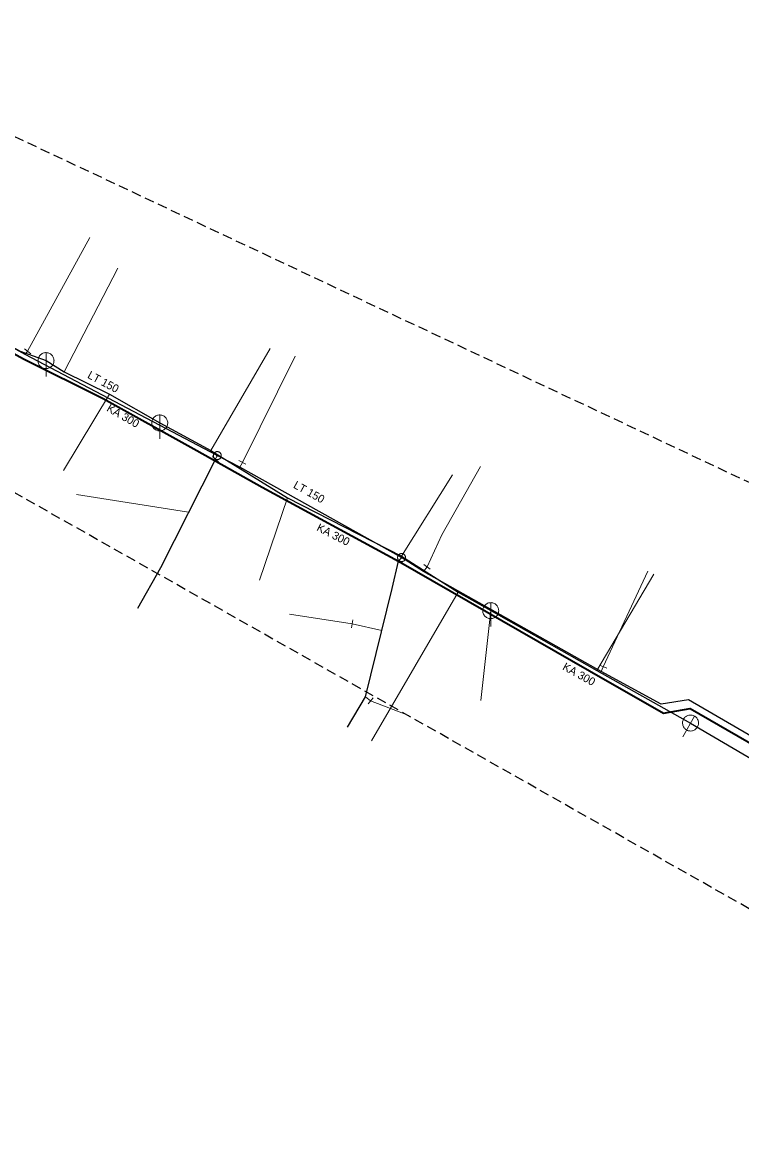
# Model space of a CAD drawing. Extents: x -749365 to -748625, y -965388 to -964881.
# Drawn here: x -749302.4 to -749212.4, y -965022.6 to -964883.5 of the extents above; entities that cross this region are included whole.
import ezdxf

# ---------------------------------------------------------------- set-up
doc = ezdxf.new("R2010")
doc.units = 0
doc.header["$LTSCALE"] = 0.4
doc.linetypes.add('MEDIUM_DASHED', pattern=[4.5, 3, -1.5])
for name, color, linetype, lineweight in [('1', 7, 'MEDIUM_DASHED', 25), ('11', 7, 'Continuous', 13), ('13', 7, 'Continuous', 13), ('14', 7, 'Continuous', 13), ('17', 7, 'Continuous', 25), ('22', 7, 'Continuous', 13), ('34', 7, 'Continuous', 13), ('47', 7, 'Continuous', 13)]:
    doc.layers.add(name, color=color, linetype=linetype, lineweight=lineweight)

msp = doc.modelspace()

# ---------------------------------------------------------------- linework, layer by layer
at = {"layer": '1'}
msp.add_lwpolyline([(-748913.896, -965162.751), (-749358.2, -964911.234), (-749358.98, -964910.689), (-749359.642, -964910.006), (-749360.163, -964909.209), (-749360.523, -964908.329), (-749360.711, -964907.396), (-749360.718, -964906.445), (-749360.545, -964905.509), (-749360.198, -964904.624), (-749359.689, -964903.82), (-749359.037, -964903.126), (-749338.098, -964884.732), (-749337.314, -964884.168), (-749336.437, -964883.765), (-749335.498, -964883.538), (-749334.533, -964883.496), (-749333.578, -964883.64), (-749332.669, -964883.965), (-749106.184, -964990.559)], dxfattribs=at)
at = {"layer": '11'}
for p, q in [((-749290.446, -964914.223), (-749297.169, -964927.173)), ((-749271.406, -964924.25), (-749278.819, -964937.006)), ((-749297.227, -964939.522), (-749291.482, -964929.991)), ((-749248.579, -964940.069), (-749254.979, -964950.219)), ((-749272.719, -964953.233), (-749269.224, -964942.92)), ((-749223.424, -964952.476), (-749230.566, -964964.516)), ((-749258.738, -964973.284), (-749247.897, -964954.719)), ((-749245.037, -964968.248), (-749243.82, -964957.026))]:
    msp.add_line(p, q, dxfattribs=at)
at = {"layer": '13'}
for p, q in [((-749301.726, -964924.619), (-749293.96, -964910.397)), ((-749274.864, -964938.499), (-749268.259, -964925.237)), ((-749281.584, -964944.718), (-749295.599, -964942.529)), ((-749229.753, -964964.03), (-749224.188, -964952.096)), ((-749261.132, -964958.688), (-749268.993, -964957.445)), ((-749257.417, -964959.516), (-749261.132, -964958.688)), ((-749258.835, -964968.296), (-749254.048, -964970.135))]:
    msp.add_line(p, q, dxfattribs=at)
msp.add_lwpolyline([(-749251.775, -964951.544), (-749249.923, -964947.552), (-749245.094, -964939.009)], dxfattribs=at)
at = {"layer": '14'}
for p, q in [((-749302.022, -964925.022), (-749301.726, -964924.619)), ((-749278.003, -964937.651), (-749278.231, -964938.107)), ((-749275.193, -964939.098), (-749274.864, -964938.499)), ((-749254.966, -964950.395), (-749255.339, -964950.843)), ((-749252.214, -964952.116), (-749251.775, -964951.544)), ((-749229.989, -964964.651), (-749229.753, -964964.03)), ((-749259.462, -964967.8), (-749258.835, -964968.296))]:
    msp.add_line(p, q, dxfattribs=at)
at = {"layer": '14', "lineweight": 25}
for points in [[(-749318.67, -964914.98), (-749315.285, -964917.793), (-749302.649, -964924.581), (-749299.42, -964925.78)], [(-749299.42, -964925.78), (-749297.169, -964927.173), (-749291.482, -964929.991), (-749285.199, -964933.57)], [(-749285.199, -964933.57), (-749278.818, -964937.006), (-749269.224, -964942.92), (-749254.978, -964950.219), (-749247.897, -964954.719), (-749243.82, -964957.026)], [(-749243.82, -964957.026), (-749230.566, -964964.515), (-749218.834, -964971.068)], [(-749218.834, -964971.068), (-749209.362, -964976.622), (-749191.809, -964986.765), (-749189.541, -964988.087), (-749180.034, -964993.011)]]:
    msp.add_lwpolyline(points, dxfattribs=at)
at = {"layer": '17', "lineweight": 35}
msp.add_lwpolyline([(-749338.07, -964901.664), (-749339.897, -964904.533), (-749328.89, -964910.512), (-749320.106, -964915.328), (-749306.348, -964923.318), (-749302.22, -964925.541), (-749292.258, -964930.514), (-749280.577, -964937.024), (-749272.375, -964941.575), (-749255.349, -964950.855), (-749231.471, -964964.54), (-749222.21, -964969.832), (-749218.876, -964969.25), (-749196.521, -964982.106)], dxfattribs=at)
at = {"layer": '17'}
for points in [[(-749278.003, -964937.651), (-749302.022, -964925.022), (-749306.274, -964922.687)], [(-749278.231, -964938.107), (-749285.12, -964951.69), (-749287.963, -964956.74)], [(-749254.966, -964950.395), (-749275.193, -964939.098), (-749278.003, -964937.651)], [(-749261.721, -964971.596), (-749259.462, -964967.8), (-749256.123, -964954.277), (-749255.339, -964950.843)], [(-749129.897, -965019.83), (-749141.763, -965012.953), (-749147.67, -965009.555), (-749169.498, -964996.566), (-749174.36, -964993.689), (-749178.686, -964991.22), (-749181.107, -964990.017), (-749187.92, -964986.181), (-749197.61, -964980.691), (-749208.557, -964974.308), (-749219.081, -964968.169), (-749222.514, -964968.719), (-749229.989, -964964.651), (-749252.214, -964952.116), (-749254.966, -964950.395)]]:
    msp.add_lwpolyline(points, dxfattribs=at)
at = {"layer": '22'}
for p, q in [((-749299.42, -964927.78), (-749299.419, -964924.78)), ((-749285.199, -964935.57), (-749285.198, -964932.57)), ((-749243.82, -964959.026), (-749243.819, -964956.026)), ((-749219.809, -964972.814), (-749218.346, -964970.195))]:
    msp.add_line(p, q, dxfattribs=at)
for points in [[(-749298.42, -964925.78), (-749298.425, -964925.671), (-749298.443, -964925.563), (-749298.473, -964925.457), (-749298.513, -964925.356), (-749298.565, -964925.259), (-749298.627, -964925.169), (-749298.699, -964925.086), (-749298.779, -964925.012), (-749298.867, -964924.946), (-749298.961, -964924.891), (-749299.061, -964924.846), (-749299.166, -964924.813), (-749299.273, -964924.791), (-749299.382, -964924.781), (-749299.492, -964924.783), (-749299.6, -964924.797), (-749299.707, -964924.822), (-749299.81, -964924.859), (-749299.908, -964924.908), (-749300, -964924.966), (-749300.086, -964925.035), (-749300.163, -964925.112), (-749300.232, -964925.198), (-749300.291, -964925.29), (-749300.339, -964925.388), (-749300.376, -964925.491), (-749300.402, -964925.598), (-749300.416, -964925.706), (-749300.419, -964925.816), (-749300.409, -964925.925), (-749300.388, -964926.032), (-749300.354, -964926.136), (-749300.31, -964926.236), (-749300.255, -964926.331), (-749300.189, -964926.419), (-749300.115, -964926.499), (-749300.032, -964926.571), (-749299.942, -964926.633), (-749299.846, -964926.685), (-749299.744, -964926.726), (-749299.639, -964926.756), (-749299.531, -964926.774), (-749299.421, -964926.78), (-749299.312, -964926.774), (-749299.204, -964926.756), (-749299.099, -964926.727), (-749298.997, -964926.686), (-749298.9, -964926.634), (-749298.81, -964926.572), (-749298.727, -964926.501), (-749298.652, -964926.421), (-749298.587, -964926.333), (-749298.531, -964926.239), (-749298.487, -964926.139), (-749298.453, -964926.035), (-749298.431, -964925.927), (-749298.421, -964925.818)], [(-749284.199, -964933.57), (-749284.204, -964933.461), (-749284.222, -964933.353), (-749284.252, -964933.247), (-749284.292, -964933.146), (-749284.344, -964933.049), (-749284.406, -964932.959), (-749284.478, -964932.876), (-749284.558, -964932.802), (-749284.646, -964932.736), (-749284.74, -964932.681), (-749284.84, -964932.636), (-749284.945, -964932.603), (-749285.052, -964932.581), (-749285.161, -964932.571), (-749285.271, -964932.573), (-749285.379, -964932.587), (-749285.486, -964932.612), (-749285.589, -964932.649), (-749285.687, -964932.698), (-749285.779, -964932.756), (-749285.865, -964932.825), (-749285.942, -964932.902), (-749286.011, -964932.988), (-749286.07, -964933.08), (-749286.118, -964933.178), (-749286.155, -964933.281), (-749286.181, -964933.388), (-749286.195, -964933.496), (-749286.198, -964933.606), (-749286.188, -964933.715), (-749286.167, -964933.822), (-749286.133, -964933.926), (-749286.089, -964934.026), (-749286.034, -964934.121), (-749285.968, -964934.209), (-749285.894, -964934.289), (-749285.811, -964934.361), (-749285.721, -964934.423), (-749285.625, -964934.475), (-749285.523, -964934.516), (-749285.418, -964934.546), (-749285.31, -964934.564), (-749285.2, -964934.57), (-749285.091, -964934.564), (-749284.983, -964934.546), (-749284.878, -964934.517), (-749284.776, -964934.476), (-749284.679, -964934.424), (-749284.589, -964934.362), (-749284.506, -964934.291), (-749284.431, -964934.211), (-749284.366, -964934.123), (-749284.31, -964934.029), (-749284.266, -964933.929), (-749284.232, -964933.825), (-749284.21, -964933.717), (-749284.2, -964933.608)], [(-749242.82, -964957.026), (-749242.825, -964956.917), (-749242.843, -964956.809), (-749242.873, -964956.703), (-749242.913, -964956.602), (-749242.965, -964956.505), (-749243.027, -964956.415), (-749243.099, -964956.332), (-749243.179, -964956.258), (-749243.267, -964956.192), (-749243.361, -964956.137), (-749243.461, -964956.092), (-749243.566, -964956.059), (-749243.673, -964956.037), (-749243.782, -964956.027), (-749243.892, -964956.029), (-749244, -964956.043), (-749244.107, -964956.068), (-749244.21, -964956.105), (-749244.308, -964956.154), (-749244.4, -964956.212), (-749244.486, -964956.281), (-749244.563, -964956.358), (-749244.632, -964956.444), (-749244.691, -964956.536), (-749244.739, -964956.634), (-749244.776, -964956.737), (-749244.802, -964956.844), (-749244.816, -964956.952), (-749244.819, -964957.062), (-749244.809, -964957.171), (-749244.788, -964957.278), (-749244.754, -964957.382), (-749244.71, -964957.482), (-749244.655, -964957.577), (-749244.589, -964957.665), (-749244.515, -964957.745), (-749244.432, -964957.817), (-749244.342, -964957.879), (-749244.246, -964957.931), (-749244.144, -964957.972), (-749244.039, -964958.002), (-749243.931, -964958.02), (-749243.821, -964958.026), (-749243.712, -964958.02), (-749243.604, -964958.002), (-749243.499, -964957.973), (-749243.397, -964957.932), (-749243.3, -964957.88), (-749243.21, -964957.818), (-749243.127, -964957.747), (-749243.052, -964957.667), (-749242.987, -964957.579), (-749242.931, -964957.485), (-749242.887, -964957.385), (-749242.853, -964957.281), (-749242.831, -964957.173), (-749242.821, -964957.064)], [(-749217.961, -964971.556), (-749217.913, -964971.457), (-749217.876, -964971.354), (-749217.85, -964971.247), (-749217.836, -964971.14), (-749217.834, -964971.029), (-749217.844, -964970.921), (-749217.867, -964970.813), (-749217.9, -964970.71), (-749217.945, -964970.609), (-749218, -964970.515), (-749218.066, -964970.427), (-749218.141, -964970.347), (-749218.224, -964970.276), (-749218.314, -964970.214), (-749218.411, -964970.162), (-749218.512, -964970.121), (-749218.618, -964970.091), (-749218.726, -964970.073), (-749218.835, -964970.068), (-749218.944, -964970.074), (-749219.053, -964970.092), (-749219.158, -964970.122), (-749219.26, -964970.163), (-749219.356, -964970.215), (-749219.446, -964970.277), (-749219.528, -964970.349), (-749219.603, -964970.43), (-749219.668, -964970.517), (-749219.723, -964970.612), (-749219.768, -964970.712), (-749219.802, -964970.816), (-749219.823, -964970.923), (-749219.833, -964971.032), (-749219.831, -964971.142), (-749219.817, -964971.251), (-749219.791, -964971.357), (-749219.754, -964971.46), (-749219.705, -964971.558), (-749219.647, -964971.65), (-749219.578, -964971.736), (-749219.501, -964971.813), (-749219.415, -964971.882), (-749219.322, -964971.941), (-749219.224, -964971.988), (-749219.121, -964972.025), (-749219.015, -964972.051), (-749218.906, -964972.065), (-749218.796, -964972.067), (-749218.687, -964972.057), (-749218.58, -964972.035), (-749218.476, -964972.002), (-749218.376, -964971.957), (-749218.281, -964971.902), (-749218.194, -964971.836), (-749218.114, -964971.762), (-749218.042, -964971.679), (-749217.98, -964971.588)]]:
    msp.add_lwpolyline(points, close=True, dxfattribs=at)
at = {"layer": '34'}
for p, q in [((-749302.129, -964924.324), (-749301.322, -964924.914)), ((-749277.866, -964938.449), (-749278.594, -964937.763)), ((-749275.302, -964938.259), (-749274.425, -964938.739)), ((-749255.826, -964950.733), (-749254.851, -964950.953)), ((-749252.171, -964951.239), (-749251.378, -964951.848)), ((-749261.054, -964958.194), (-749261.21, -964959.181)), ((-749230.22, -964963.853), (-749229.285, -964964.207)), ((-749258.525, -964967.903), (-749259.145, -964968.687))]:
    msp.add_line(p, q, dxfattribs=at)
at = {"layer": '47'}
for points in [[(-749278.226, -964938.098), (-749278.178, -964938.118), (-749278.128, -964938.134), (-749278.077, -964938.144), (-749278.025, -964938.15), (-749277.973, -964938.15), (-749277.92, -964938.143), (-749277.87, -964938.132), (-749277.82, -964938.115), (-749277.773, -964938.094), (-749277.727, -964938.068), (-749277.685, -964938.036), (-749277.647, -964938.001), (-749277.612, -964937.962), (-749277.581, -964937.919), (-749277.555, -964937.874), (-749277.535, -964937.826), (-749277.519, -964937.776), (-749277.508, -964937.724), (-749277.503, -964937.673), (-749277.503, -964937.621), (-749277.51, -964937.568), (-749277.521, -964937.517), (-749277.537, -964937.467), (-749277.558, -964937.42), (-749277.585, -964937.375), (-749277.617, -964937.333), (-749277.652, -964937.294), (-749277.691, -964937.26), (-749277.734, -964937.229), (-749277.779, -964937.203), (-749277.827, -964937.183), (-749277.877, -964937.167), (-749277.928, -964937.155), (-749277.98, -964937.151), (-749278.032, -964937.151), (-749278.084, -964937.157), (-749278.136, -964937.168), (-749278.185, -964937.185), (-749278.233, -964937.206), (-749278.278, -964937.233), (-749278.32, -964937.265), (-749278.359, -964937.299), (-749278.393, -964937.339), (-749278.424, -964937.382), (-749278.45, -964937.427), (-749278.47, -964937.475), (-749278.486, -964937.525), (-749278.497, -964937.575), (-749278.502, -964937.628), (-749278.502, -964937.68), (-749278.496, -964937.732), (-749278.485, -964937.783), (-749278.468, -964937.833), (-749278.446, -964937.88), (-749278.42, -964937.926), (-749278.388, -964937.968), (-749278.354, -964938.006), (-749278.314, -964938.041), (-749278.271, -964938.072)], [(-749278.039, -964937.724), (-749278.031, -964937.728), (-749278.023, -964937.73), (-749278.015, -964937.731), (-749278.007, -964937.732), (-749277.998, -964937.732), (-749277.989, -964937.731), (-749277.981, -964937.73), (-749277.973, -964937.727), (-749277.965, -964937.723), (-749277.957, -964937.719), (-749277.95, -964937.714), (-749277.944, -964937.708), (-749277.939, -964937.701), (-749277.933, -964937.695), (-749277.929, -964937.687), (-749277.925, -964937.679), (-749277.923, -964937.671), (-749277.922, -964937.663), (-749277.921, -964937.655), (-749277.921, -964937.646), (-749277.922, -964937.637), (-749277.923, -964937.629), (-749277.926, -964937.621), (-749277.93, -964937.612), (-749277.934, -964937.605), (-749277.939, -964937.598), (-749277.945, -964937.592), (-749277.952, -964937.587), (-749277.958, -964937.581), (-749277.966, -964937.577), (-749277.974, -964937.573), (-749277.982, -964937.571), (-749277.99, -964937.57), (-749277.998, -964937.569), (-749278.007, -964937.569), (-749278.015, -964937.569), (-749278.024, -964937.571), (-749278.032, -964937.574), (-749278.041, -964937.578), (-749278.048, -964937.582), (-749278.055, -964937.587), (-749278.061, -964937.593), (-749278.066, -964937.6), (-749278.072, -964937.606), (-749278.076, -964937.614), (-749278.08, -964937.622), (-749278.082, -964937.63), (-749278.083, -964937.638), (-749278.084, -964937.646), (-749278.084, -964937.655), (-749278.084, -964937.663), (-749278.082, -964937.672), (-749278.079, -964937.68), (-749278.075, -964937.688), (-749278.071, -964937.696), (-749278.066, -964937.703), (-749278.06, -964937.709), (-749278.053, -964937.714), (-749278.047, -964937.72)], [(-749255.285, -964950.779), (-749255.243, -964950.81), (-749255.198, -964950.837), (-749255.151, -964950.858), (-749255.102, -964950.876), (-749255.05, -964950.887), (-749254.998, -964950.893), (-749254.946, -964950.893), (-749254.894, -964950.889), (-749254.843, -964950.879), (-749254.793, -964950.864), (-749254.744, -964950.843), (-749254.699, -964950.817), (-749254.656, -964950.787), (-749254.617, -964950.752), (-749254.581, -964950.714), (-749254.55, -964950.672), (-749254.523, -964950.627), (-749254.501, -964950.579), (-749254.484, -964950.531), (-749254.473, -964950.479), (-749254.467, -964950.427), (-749254.466, -964950.374), (-749254.471, -964950.322), (-749254.48, -964950.271), (-749254.496, -964950.222), (-749254.517, -964950.173), (-749254.543, -964950.127), (-749254.573, -964950.085), (-749254.608, -964950.046), (-749254.646, -964950.01), (-749254.688, -964949.979), (-749254.733, -964949.952), (-749254.78, -964949.929), (-749254.829, -964949.913), (-749254.881, -964949.902), (-749254.932, -964949.895), (-749254.985, -964949.894), (-749255.037, -964949.899), (-749255.089, -964949.909), (-749255.138, -964949.925), (-749255.187, -964949.946), (-749255.232, -964949.971), (-749255.275, -964950.002), (-749255.314, -964950.037), (-749255.35, -964950.075), (-749255.381, -964950.117), (-749255.408, -964950.162), (-749255.43, -964950.208), (-749255.447, -964950.258), (-749255.458, -964950.31), (-749255.465, -964950.361), (-749255.465, -964950.413), (-749255.46, -964950.465), (-749255.45, -964950.517), (-749255.435, -964950.567), (-749255.414, -964950.616), (-749255.389, -964950.66), (-749255.358, -964950.704), (-749255.323, -964950.743)], [(-749255.018, -964950.458), (-749255.011, -964950.463), (-749255.004, -964950.467), (-749254.996, -964950.47), (-749254.988, -964950.473), (-749254.979, -964950.475), (-749254.971, -964950.476), (-749254.962, -964950.477), (-749254.954, -964950.476), (-749254.945, -964950.474), (-749254.937, -964950.471), (-749254.929, -964950.468), (-749254.922, -964950.464), (-749254.915, -964950.459), (-749254.908, -964950.454), (-749254.902, -964950.447), (-749254.897, -964950.44), (-749254.893, -964950.433), (-749254.89, -964950.425), (-749254.887, -964950.417), (-749254.885, -964950.408), (-749254.884, -964950.4), (-749254.883, -964950.391), (-749254.884, -964950.383), (-749254.886, -964950.374), (-749254.889, -964950.366), (-749254.892, -964950.358), (-749254.896, -964950.351), (-749254.901, -964950.344), (-749254.906, -964950.337), (-749254.913, -964950.331), (-749254.92, -964950.326), (-749254.927, -964950.322), (-749254.935, -964950.319), (-749254.943, -964950.316), (-749254.952, -964950.314), (-749254.96, -964950.312), (-749254.969, -964950.312), (-749254.977, -964950.313), (-749254.986, -964950.315), (-749254.994, -964950.318), (-749255.002, -964950.321), (-749255.009, -964950.325), (-749255.016, -964950.33), (-749255.023, -964950.335), (-749255.029, -964950.342), (-749255.034, -964950.349), (-749255.038, -964950.356), (-749255.041, -964950.364), (-749255.044, -964950.372), (-749255.046, -964950.381), (-749255.048, -964950.389), (-749255.048, -964950.398), (-749255.047, -964950.406), (-749255.045, -964950.415), (-749255.042, -964950.423), (-749255.039, -964950.431), (-749255.035, -964950.438), (-749255.03, -964950.445), (-749255.025, -964950.452)]]:
    msp.add_lwpolyline(points, close=True, dxfattribs=at)

# ---------------------------------------------------------------- texts
at = {"layer": '1'}
for s, rotation, p in [('LT 150', 332, (-749294.328, -964927.894)), ('KA 300', 330, (-749291.93, -964932.02)), ('LT 150', 331, (-749268.587, -964941.626)), ('KA 300', 333, (-749265.675, -964946.967)), ('KA 300', 331, (-749234.932, -964964.339))]:
    msp.add_text(s, height=1, rotation=rotation, dxfattribs=at).set_placement(p)

doc.saveas('drawing.dxf')
